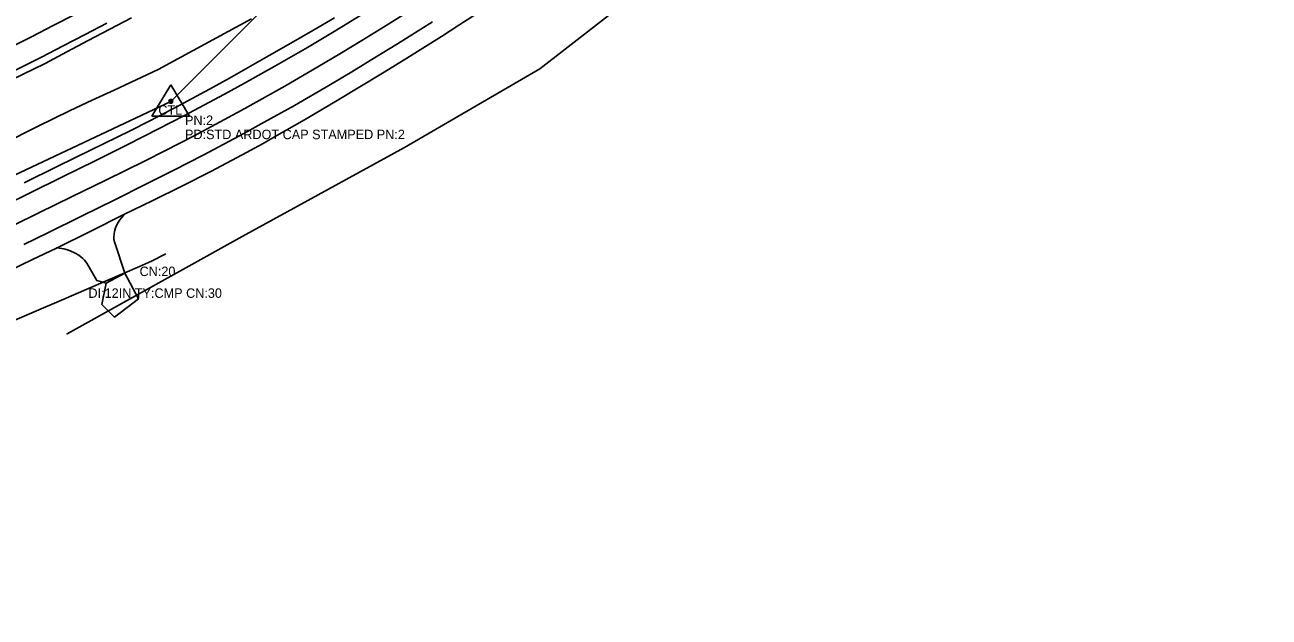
# Model space of a CAD drawing. Extents: x 1676038 to 1677961, y 226475 to 233854.
# Drawn here: x 1676549 to 1677207, y 227374 to 227687 of the extents above; entities that cross this region are included whole.
import ezdxf

# ---------------------------------------------------------------- set-up
doc = ezdxf.new("R2010")
doc.units = 0
for name, color, linetype in [('S_BASELINE', 7, 'Continuous'), ('S_DITCHLINE', 7, 'Continuous'), ('S_DRG_PT_SYM', 7, 'Continuous'), ('S_EDGE_BITUMINOUS', 7, 'Continuous'), ('S_EDGE_PAVEMENT', 7, 'Continuous'), ('S_FIBER_OPTIC_CABLE', 7, 'Continuous'), ('S_GRAVEL_ROAD', 7, 'Continuous'), ('S_PAVEMENT_CROWN', 7, 'Continuous'), ('S_PRIMARY_CTL', 7, 'Continuous'), ('S_PRIMARY_CTL_ANNOT', 7, 'Continuous'), ('S_SHOULDER', 7, 'Continuous'), ('S_SIDE_DRAIN', 7, 'Continuous'), ('S_SIDE_DRAIN_ANNOT', 7, 'Continuous'), ('S_UTL_PT_SYM', 7, 'Continuous')]:
    doc.layers.add(name, color=color, linetype=linetype)

msp = doc.modelspace()

# ---------------------------------------------------------------- linework, layer by layer
at = {"layer": 'S_BASELINE'}
for p, q in [((1676625.89, 227646.73), (1677368.16, 228389.18)), ((1676048.3, 227373.82), (1676625.89, 227646.73))]:
    msp.add_line(p, q, dxfattribs=at)
at = {"layer": 'S_DITCHLINE'}
for points in [[(1676537.51, 227624.49), (1676555.07, 227633.23), (1676572.63, 227641.96), (1676584.27, 227647.35), (1676595.92, 227652.74), (1676607.56, 227658.13), (1676619.21, 227663.52), (1676631.55, 227670.24), (1676643.88, 227676.95), (1676656.22, 227683.66), (1676668.56, 227690.37)], [(1676609.37, 227559.28), (1676615.59, 227562.13), (1676623.22, 227566.02)], [(1676525.02, 227522.93), (1676539.36, 227529.14), (1676553.7, 227535.35), (1676568.05, 227541.57), (1676582.39, 227547.78)]]:
    msp.add_lwpolyline(points, dxfattribs=at)
at = {"layer": 'S_DRG_PT_SYM'}
for points in [[(1676609.36, 227559.29), (1676609.36, 227559.34), (1676609.36, 227559.29), (1676609.31, 227559.29), (1676609.36, 227559.29), (1676609.36, 227559.24), (1676609.36, 227559.29), (1676609.41, 227559.29)], [(1676582.33, 227547.77), (1676582.33, 227547.82), (1676582.33, 227547.77), (1676582.28, 227547.77), (1676582.33, 227547.77), (1676582.33, 227547.72), (1676582.33, 227547.77), (1676582.38, 227547.77)]]:
    msp.add_lwpolyline(points, dxfattribs=at)
at = {"layer": 'S_EDGE_BITUMINOUS'}
msp.add_lwpolyline([(1676565.47, 227569.19), (1676568.08, 227568.88), (1676569.36, 227568.62), (1676571.23, 227568.11), (1676572.62, 227567.63), (1676575.32, 227566.41), (1676577.23, 227565.29), (1676579.37, 227563.67), (1676580.32, 227562.72), (1676581.5, 227561.06), (1676586.68, 227551.9), (1676591.69, 227550.55), (1676601.59, 227555.91), (1676596.21, 227571.95), (1676595.83, 227573.59), (1676595.74, 227574.69), (1676595.89, 227576.87), (1676596.28, 227578.65), (1676596.66, 227579.8), (1676597.65, 227582.02), (1676599, 227584.13), (1676599.79, 227585.11), (1676601.13, 227586.51)], dxfattribs=at)
at = {"layer": 'S_EDGE_PAVEMENT'}
for points in [[(1676538.2, 227591.77), (1676551.13, 227598.08), (1676568.66, 227606.72), (1676586.18, 227615.36), (1676601.78, 227623.14), (1676612.15, 227628.41), (1676632.78, 227639.12), (1676654.24, 227650.56), (1676664.91, 227656.39), (1676680.84, 227665.29), (1676698.16, 227675.29), (1676709.63, 227682.09), (1676717.25, 227686.68), (1676732.39, 227696.01)], [(1676539.8, 227661.38), (1676557.45, 227670.2), (1676569.01, 227676.18), (1676580.56, 227682.15), (1676592.12, 227688.13)], [(1676548.18, 227570.98), (1676560.83, 227577.13), (1676578.71, 227586.01), (1676596.58, 227594.89), (1676612.06, 227602.64), (1676627.54, 227610.4), (1676642.93, 227618.31), (1676664.53, 227629.77), (1676675.26, 227635.64), (1676691.25, 227644.62), (1676709.54, 227655.21), (1676721.65, 227662.42), (1676733.68, 227669.77), (1676745.7, 227677.12), (1676764.28, 227688.81)]]:
    msp.add_lwpolyline(points, dxfattribs=at)
at = {"layer": 'S_FIBER_OPTIC_CABLE'}
for p, q in [((1676821.12, 227663.91), (1676864.37, 227697.61)), ((1676749.48, 227622.29), (1676821.12, 227663.91)), ((1676663.58, 227575.17), (1676749.48, 227622.29)), ((1676571.02, 227523.73), (1676663.58, 227575.17))]:
    msp.add_line(p, q, dxfattribs=at)
at = {"layer": 'S_GRAVEL_ROAD'}
msp.add_lwpolyline([(1676591.68, 227550.52), (1676589.46, 227539.26), (1676596.1, 227532.59), (1676608.73, 227542.23), (1676601.59, 227555.91)], dxfattribs=at)
at = {"layer": 'S_PAVEMENT_CROWN'}
for points in [[(1676543.22, 227581.48), (1676556.06, 227587.76), (1676573.76, 227596.39), (1676591.46, 227605.03), (1676612.34, 227615.32), (1676622.73, 227620.55), (1676638.25, 227628.53), (1676654.34, 227637.08), (1676665.01, 227642.9), (1676686.19, 227654.8), (1676703.71, 227665), (1676715.33, 227671.91), (1676726.88, 227678.95), (1676738.42, 227685.98), (1676757.29, 227697.82)], [(1676534.44, 227672.12), (1676552.19, 227680.94), (1676563.62, 227686.84), (1676575.04, 227692.73)]]:
    msp.add_lwpolyline(points, dxfattribs=at)
at = {"layer": 'S_PRIMARY_CTL'}
for p, q in [((1676625.89, 227655.43), (1676615.86, 227638.92)), ((1676625.89, 227655.43), (1676635.71, 227638.92)), ((1676615.86, 227638.92), (1676635.71, 227638.92))]:
    msp.add_line(p, q, dxfattribs=at)
for radius in [1.04, 0.609, 0.344]:
    msp.add_circle((1676625.89, 227646.73), radius, dxfattribs=at)
at = {"layer": 'S_SHOULDER'}
for points in [[(1676540.01, 227556.81), (1676552.71, 227562.97), (1676565.42, 227569.13), (1676583.22, 227577.95), (1676601.03, 227586.78), (1676616.37, 227594.33), (1676631.71, 227601.87), (1676646.97, 227609.58), (1676663.66, 227618.43), (1676674.69, 227624.51), (1676682.01, 227628.63), (1676696.58, 227636.99), (1676714.73, 227647.66), (1676726.77, 227654.88), (1676738.73, 227662.21), (1676750.7, 227669.55), (1676769.11, 227681.11), (1676778.26, 227686.98), (1676791.9, 227695.91)], [(1676541.58, 227658.04), (1676559.43, 227666.82), (1676570.84, 227672.86), (1676582.26, 227678.89), (1676593.67, 227684.93), (1676605.09, 227690.97)], [(1676548.32, 227603.63), (1676565.85, 227612.23), (1676583.38, 227620.83), (1676604.35, 227631.17), (1676614.79, 227636.43), (1676630.34, 227644.5), (1676646.28, 227653.15), (1676656.84, 227659.05), (1676677.87, 227671.01), (1676689.41, 227677.6), (1676700.95, 227684.2), (1676712.44, 227690.88)]]:
    msp.add_lwpolyline(points, dxfattribs=at)
at = {"layer": 'S_SIDE_DRAIN'}
msp.add_line((1676582.33, 227547.77), (1676609.36, 227559.29), dxfattribs=at)
at = {"layer": 'S_UTL_PT_SYM'}
for points in [[(1676821.12, 227663.91), (1676821.12, 227663.96), (1676821.12, 227663.91), (1676821.07, 227663.91), (1676821.12, 227663.91), (1676821.12, 227663.86), (1676821.12, 227663.91), (1676821.17, 227663.91)], [(1676749.48, 227622.29), (1676749.48, 227622.34), (1676749.48, 227622.29), (1676749.43, 227622.29), (1676749.48, 227622.29), (1676749.48, 227622.24), (1676749.48, 227622.29), (1676749.53, 227622.29)], [(1676663.58, 227575.17), (1676663.58, 227575.22), (1676663.58, 227575.17), (1676663.53, 227575.17), (1676663.58, 227575.17), (1676663.58, 227575.12), (1676663.58, 227575.17), (1676663.63, 227575.17)], [(1676571.02, 227523.73), (1676571.02, 227523.78), (1676571.02, 227523.73), (1676570.97, 227523.73), (1676571.02, 227523.73), (1676571.02, 227523.68), (1676571.02, 227523.73), (1676571.07, 227523.73)]]:
    msp.add_lwpolyline(points, dxfattribs=at)

# ---------------------------------------------------------------- texts
at = {"layer": 'S_PRIMARY_CTL'}
msp.add_text('CTL', height=5, rotation=360, dxfattribs=at).set_placement((1676619.3, 227639.65))
at = {"layer": 'S_PRIMARY_CTL_ANNOT'}
for s, p in [('PN:2', (1676633.39, 227634.23)), ('PD:STD ARDOT CAP STAMPED PN:2', (1676633.39, 227626.73))]:
    msp.add_text(s, height=5, dxfattribs=at).set_placement(p)
at = {"layer": 'S_SIDE_DRAIN_ANNOT'}
for s, p in [('CN:20', (1676609.36, 227554.29)), ('DI:12IN TY:CMP CN:30', (1676582.33, 227542.77))]:
    msp.add_text(s, height=5, dxfattribs=at).set_placement(p)

doc.saveas('drawing.dxf')
